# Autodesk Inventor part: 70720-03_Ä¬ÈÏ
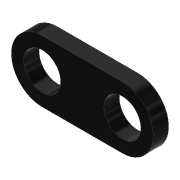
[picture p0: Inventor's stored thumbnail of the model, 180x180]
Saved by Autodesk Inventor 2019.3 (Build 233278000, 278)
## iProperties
Created: 2010-06
Part Number: 70720-03_Ä¬ÈÏ
Material: Ogólny
Document SubType Name: Modeling
Designer: CADENGINEERING4
Density: 1 g/cm^3
Appearance: Gładki — czarny
Author: CADENGINEERING4
Revision Number: ÈÎºÎ
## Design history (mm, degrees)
feature "NONE"
node "Bryła1"
